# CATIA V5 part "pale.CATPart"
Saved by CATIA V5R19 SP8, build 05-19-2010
Part number: Pales et axe
Bounding box of the stored display mesh (mm): x -400.868 to 620.068, y -893.533 to 20.003, z -431.861 to 500
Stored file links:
  G:\EU_thinkMotion\CFAO_2010\St2M_groupe2\St2M_groupe2\npeyre\npeyre\pale.CATPart
  C:\Documents and Settings\Niels\Mes documents\IFMA\2A\Calculs et CFAO\Modélisation eolienne axe vertical\eolienne avec train reducteur\assemblage.CATProduct
  G:\EU_thinkMotion\CFAO_2010\St2M_groupe2\St2M_groupe2\npeyre\npeyre\alesage axe rotor.CATPart
  G:\EU_thinkMotion\CFAO_2010\St2M_groupe2\St2M_groupe2\npeyre\npeyre\sortie vers generateur.CATPart
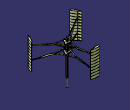
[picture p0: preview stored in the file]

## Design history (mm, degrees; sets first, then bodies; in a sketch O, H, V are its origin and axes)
Parameters
  `Longueur pale suivant Z` = 500 mm
  `Distance pale axe` = 500 mm
  `Diametre depart accroche pale` = 10 mm
  `Diametre interne accroche pale ` = 25 mm
  `Diametre des tiges d'accroche internes` = 11.1111 mm {= `Diametre interne accroche pale ` *4/9}
  `empatement des tiges d'accroche internes` = 130 mm
  `Hauteur du premier triangle rotor` = 600 mm
  `Diametre axe rotor` = 30 mm
  `Distance pale-division accroche (en % de la distance axe pale)` = 70 (ratio)
Sketch1 on xy-plane, origin (0, 0, 0), H (1, 0, 0), V (0, 1, 0)
  line L1 (34.746, -500) -> (164.746, -500)
  point P2 (164.746, -500)
  line L2 (164.746, -500) -> (99.746, -612.5833)
  line L3 (99.746, -612.5833) -> (34.746, -500)
  reference projected line E1 (-5.254, -500) -> (194.746, -500) from Sketch2.L3
  reference projected point E2 (164.746, -500) from vertex [element of Sketch2 | element of Sketch2]
  length L2 = 130 {= `empatement des tiges d'accroche internes`}
  length L3 = 130 {= `empatement des tiges d'accroche internes`}
  length L1 = 130 {= `empatement des tiges d'accroche internes`}
  horizontal: L1 H
  coincidence: L1 E1, P2 E2
Sketch2 on Plane3, origin (0, -500, 0), H (-1, 0, 0), V (0, 0, 1)
  line L1 (-34.746, 157.0283) -> (-164.746, 157.0283)
  line L2 (-164.746, 157.0283) -> (-164.746, 168.1394)
  line L3 (-164.746, 168.1394) -> (-34.746, 168.1394)
  line L4 (-34.746, 168.1394) -> (-34.746, 157.0283)
  reference projected circle E1 centre (-105.3016, 162.5839) radius 5.5556 from Sketch5.A1
  reference projected circle E2 centre (-105.3016, 162.5839) radius 5.5556 from Sketch5.A1
  reference projected line E3 through (-99.746, 0) direction (0, 1) from Line1
  distance L4 L2 = 130 {= `empatement des tiges d'accroche internes`}
  distance L4 E3 = 65 {= `empatement des tiges d'accroche internes` /2}
  horizontal: L1 H, L3 H
  vertical: L2 V, L4 V
  tangency: E1 L3, L1 E2
Body1 (main body)
  Point1: type OnPlane, Support xy-plane, H 0 {= `détruit_facteur d'echelle du profil` *0mm}, V 0 {= `détruit_facteur d'echelle du profil` *0mm}, Direction (1, 0, 0)
  Point2: type OnPlane, Support xy-plane, H 16.791 {= `détruit_facteur d'echelle du profil` *16.791mm}, V 14.593 {= `détruit_facteur d'echelle du profil` *14.593mm}, Direction (1, 0, 0)
  Point3: type OnPlane, Support xy-plane, H 59.666 {= `détruit_facteur d'echelle du profil` *59.666mm}, V 19.725 {= `détruit_facteur d'echelle du profil` *19.725mm}, Direction (1, 0, 0)
  Point4: type OnPlane, Support xy-plane, H 104.76 {= `détruit_facteur d'echelle du profil` *104.76mm}, V 16.638 {= `détruit_facteur d'echelle du profil` *16.638mm}, Direction (1, 0, 0)
  Point5: type OnPlane, Support xy-plane, H 169.79 {= `détruit_facteur d'echelle du profil` *169.79mm}, V 0 {= `détruit_facteur d'echelle du profil` *0mm}, Direction (1, 0, 0)
  Point6: type OnPlane, Support xy-plane, H 114.746 {= `détruit_facteur d'echelle du profil` *114.746mm}, V -8.578 {= `détruit_facteur d'echelle du profil` *-8.578mm}, Direction (1, 0, 0)
  Point7: type OnPlane, Support xy-plane, H 55.672 {= `détruit_facteur d'echelle du profil` *55.672mm}, V -13.026 {= `détruit_facteur d'echelle du profil` *-13.026mm}, Direction (1, 0, 0)
  Point8: type OnPlane, Support xy-plane, H 17.764 {= `détruit_facteur d'echelle du profil` *17.764mm}, V -11.11 {= `détruit_facteur d'echelle du profil` *-11.11mm}, Direction (1, 0, 0)
  Curve1: Elements (Point1; Point2; Point3; Point4; Point5; Point6; Point7; Point8), SemiClosure Point5
  Fill1: Boundary Curve1
  RectPattern1: of Fill1, direction 1 instances 11, spacing 50 {= `Longueur pale suivant Z` /10}, along Z axis
  Split1: ToCut Curve1, Cutting (Point6; Point5)
  Extrude1: Element1 {split ToCut Curve1, Cutting (Point6; Point5)}, Lim1 500 {= `Longueur pale suivant Z`}, Lim2 0, Direction (0, 0, 1)
  Plane1: type Offset, RefPlane zx-plane, Offset -15 {= `détruit_facteur d'echelle du profil` *-15mm}
  Sketch3 on Plane1, origin (0, -15, 0), H (-1, 0, 0), V (0, 0, 1)
    circle A1 centre (-99.746, 125) radius 5
    point P1 (-99.746, 125)
    reference projected line E1 (0, 0) -> (-169.9299, 0) from edge of Curve1
    reference projected line E2 (-114.746, 1000) -> (-114.746, 0) from edge of Extrude1
    distance P1 E1 = 125 {= `Longueur pale suivant Z` *1/4}
    distance E2 A1 = 10 {= `détruit_facteur d'echelle du profil` *10mm}
    radius A1 = 5 {= `Diametre depart accroche pale` /2}
  Extrude2: Element1 Sketch3, Lim1 0, Lim2 10, Direction Plane1, FirstUpto Extrude1
  Plane2: type Offset, RefPlane zx-plane, Offset 350 {= `Distance pale axe` *`Distance pale-division accroche (en % de la distance axe pale)`}, reversed
  Point9: type Center, Curve Sketch3
  Line1: type PtDir, RefPoint Point9, Direction Sketch3.V, Start 0, End 20
  Sketch4 on Plane2, origin (0, -350, 0), H (0, 0, 1), V (1, 0, 0)
    circle A1 centre (166.6667, 99.746) radius 12.5
    point P1 (166.6667, 99.746)
    reference projected line E1 through (0, 99.746) direction (1, 0) from Line1
    reference projected line E2 (0, 0) -> (0, 169.9299) from edge of Curve1
    distance P1 E2 = 166.6667 {= `Longueur pale suivant Z` *1/3}
    radius A1 = 12.5 {= `Diametre interne accroche pale `/2}
    coincidence: P1 E1
  Extrude3: Element1 Sketch4, Lim1 0, Lim2 4, Direction Plane2
  Blend1: StartLimit {blendlimit Curve edge of Extrude2, Point {extremum Reference edge of Extrude2, Direction (1, 2, 3)}, Support Extrude2}, EndLimit {blendlimit Curve Sketch4, Point {extremum Reference Sketch4, Direction (1, 2, 3)}, Support Extrude3}
  Fill2: Boundary edge of Extrude3
  Sketch5 on Fill2, origin (0, -354, 0), H (-1, 0, 0), V (0, 0, 1)
    circle A1 centre (-105.3016, 162.5839) radius 5.5556
    point P1 (-105.3016, 162.5839)
    point P2 (-94.1904, 162.5839)
    circle A2 centre (-94.1904, 162.5839) radius 5.5556
    circle A3 centre (-99.746, 172.2064) radius 5.5556
    point P3 (-99.746, 172.2064)
    reference projected line E1 through (-99.746, 0) direction (0, 1) from Line1
    reference projected circle E2 centre (-99.746, 166.6667) radius 12.5 from Sketch4.A1
    reference projected circle E3 centre (-99.746, 166.6667) radius 12.5 from Sketch4.A1
    axis line L1 (-105.3016, 162.5839) -> (-94.1904, 162.5839)
    point P4 (-105.3016, 162.5839)
    point P5 (-94.1904, 162.5839)
    point P6 (-99.746, 172.2064)
    radius A1 = 5.5556 {= `Diametre des tiges d'accroche internes`/2}
    radius A2 = 5.5556 {= `Diametre des tiges d'accroche internes` /2}
    radius A3 = 5.5556 {= `Diametre des tiges d'accroche internes` /2}
    distance P1 E2 = 5.6056 {= (`Diametre des tiges d'accroche internes`+0.1mm)/2}
    distance P2 E3 = 5.6056 {= (`Diametre des tiges d'accroche internes`+0.1mm)/2}
    distance P5 P6 = 11.1111 {= `Diametre des tiges d'accroche internes`}
    distance P5 P4 = 11.1111 {= `Diametre des tiges d'accroche internes`}
    coincidence: P3 E1, P5 P2, P4 P1, P6 P3
    horizontal: L1 H
  Plane3: type Offset, RefPlane zx-plane, Offset 500 {= `Distance pale axe`}, reversed
  SolidCombine1: FirstComponentProfile Sketch1, FirstComponentDirection Sketch1, SecondComponentProfile Sketch2, SecondComponentDirection Sketch2
  Sketch6 on face of SolidCombine1 from Sketch2.L3, origin (0, 0, 168.1394), H (1, 0, 0), V (0, 1, 0)
    circle A1 centre (99.746, -537.5278) radius 15
    point P1 (99.746, -537.5278)
    reference projected line E1 (-5.254, -500) -> (194.746, -500) from edge [face of SolidCombine1 from Sketch2.L3 | face of SolidCombine1 from Sketch1.L1]
    reference projected line E2 (241.2524, -857.6795) -> (341.2524, -1030.8846) from edge [face of SolidCombine1 from Sketch1.L3 | face of SolidCombine1 from Sketch2.L3]
    distance P1 E1 = 37.5278 {= `empatement des tiges d'accroche internes` *sqrt(3)/6}
    distance E2 P1 = 37.5278 {= `empatement des tiges d'accroche internes` *sqrt(3)/6}
    radius A1 = 15 {= `Diametre axe rotor` /2}
  Pad1: profile Sketch6, direction (0, 0, 1), length 600 {= `Hauteur du premier triangle rotor`}, mirrored extent
  Sketch7 on face of SolidCombine1 from Sketch1.L1, origin (0, -500, 0), H (-1, 0, 0), V (0, 0, 1)
    circle A1 centre (-40.3016, 162.5839) radius 5.5556
    point P1 (-40.3016, 162.5839)
    reference projected line E1 (-34.746, 321.9041) -> (-34.746, 335.2374) from edge [face of SolidCombine1 from Sketch1.L3 | face of SolidCombine1 from Sketch1.L1]
    reference projected line E2 (5.254, 168.1394) -> (-194.746, 168.1394) from edge [face of SolidCombine1 from Sketch2.L3 | face of SolidCombine1 from Sketch1.L1]
    reference projected line E3 (5.254, 157.0283) -> (-194.746, 157.0283) from edge [face of SolidCombine1 from Sketch1.L1 | face of SolidCombine1 from Sketch2.L1]
    point P2 (-40.3016, 162.5839)
    circle A2 centre (-159.1904, 162.5839) radius 5.5556
    point P3 (-159.1904, 162.5839)
    reference projected line E4 (5.254, 168.1394) -> (-194.746, 168.1394) from edge [face of SolidCombine1 from Sketch2.L3 | face of SolidCombine1 from Sketch1.L1]
    reference projected line E5 (5.254, 157.0283) -> (-194.746, 157.0283) from edge [face of SolidCombine1 from Sketch1.L1 | face of SolidCombine1 from Sketch2.L1]
    reference projected line E6 (-164.746, 321.9041) -> (-164.746, 335.2374) from edge [face of SolidCombine1 from Sketch1.L1 | face of SolidCombine1 from Sketch1.L2]
    point P4 (-159.1904, 162.5839)
    tangency: A1 E1, A1 E2, A1 E3, A2 E4, A2 E5, A2 E6
    coincidence: P2 P1, P4 P3
  Line2: type PtPt, FirstPoint Sketch5.P5, SecondPoint Sketch7.P2
  Extrude4: Element1 Sketch5.A2, Lim1 0, Lim2 4, Direction Line2, FirstUpto face of SolidCombine1 from Sketch1.L1
  Line3: type PtPt, FirstPoint Sketch5.P4, SecondPoint Sketch7.P4
  Extrude5: Element1 Sketch5.A1, Lim1 0, Lim2 4, Direction Line3, FirstUpto face of SolidCombine1 from Sketch1.L1
  Sketch8 on Plane3, origin (0, -500, 0), H (-1, 0, 0), V (0, 0, 1)
    line L1 (-94.1904, 236.6667) -> (-105.3016, 236.6667)
    line L2 (-105.3016, 236.6667) -> (-105.3016, 250)
    line L3 (-105.3016, 250) -> (-94.1904, 250)
    line L4 (-94.1904, 250) -> (-94.1904, 236.6667)
    reference projected line E1 (0, 0) -> (-169.9299, 0) from edge of Curve1
    point P5 (-99.746, 319.4582)
    reference projected line E2 through (-99.746, 0) direction (0, 1) from axis of face of Pad1 from Sketch6.A1
    length L1 = 11.1111 {= `Diametre des tiges d'accroche internes`}
    distance L3 E1 = 250 {= `Longueur pale suivant Z` /2}
    distance P5 L2 = 5.5556 {= `Diametre des tiges d'accroche internes` /2}
    horizontal: L1 H, L3 H
    vertical: L2 V, L4 V
    coincidence: P5 E2
  Pad2: profile Sketch8, direction (0, -1, 0), up to face of Pad1 from Sketch6.A1
  Point10: type OnSurface, Support start face of Pad2, Length 0, Direction Y axis
  Line4: type PtPt, FirstPoint Point10, SecondPoint Sketch5.P6
  Extrude6: Element1 Sketch5.A3, Lim1 0, Lim2 4, Direction Line4, FirstUpto start face of Pad2, SecondUpto vertex [face of Fill2]
  Blend2: StartLimit {blendlimit Curve edge of Extrude6, Point {extremum Reference edge of Extrude6, Direction (1, 2, 3)}, Support Extrude6}, EndLimit {blendlimit Curve Sketch5.A3, Point {extremum Reference Sketch5.A3, Direction (1, 2, 3)}, Support Fill2}
  MultiSel1
  Plane4: type Offset, RefPlane xy-plane, Offset 400 {= `Longueur pale suivant Z` *0.8}
  Sketch9 on Plane4, origin (0, 0, 400), H (1, 0, 0), V (0, 1, 0)
    line L1 (0, 0) -> (0, -1000)
    length L1 = 1000 {= `Distance pale axe` *2}
    vertical: L1 V
  Extrude7: Element1 Sketch9, Lim1 0, Lim2 500 {= `Distance pale axe`}, Direction Sketch7.H
  Split2: ToCut {symmetry ToTransfor Pad2, Reference face of Pad2 from Sketch8.L3}, Cutting Extrude7, Intersections {intersect ToIntersect1 {symmetry ToTransfor Pad2, Reference face of Pad2 from Sketch8.L3}, ToIntersect2 Extrude7}
  Split3: SplitPlane Extrude7
  AxisLine1: Element {intersect ToIntersect1 {symmetry ToTransfor Pad2, Reference face of Pad2 from Sketch8.L3}, ToIntersect2 Extrude7}
  Join1: Elements (Extrude1; RectPattern1; {symmetry ToTransfor Extrude2, Reference face of Pad2 from Sketch8.L3}; {symmetry ToTransfor Blend1, Reference face of Pad2 from Sketch8.L3}; {symmetry ToTransfor Extrude3, Reference face of Pad2 from Sketch8.L3}; {symmetry ToTransfor Blend2, Reference face of Pad2 from Sketch8.L3}; {symmetry ToTransfor Extrude6, Reference face of Pad2 from Sketch8.L3}; {symmetry ToTransfor Extrude4, Reference face of Pad2 from Sketch8.L3}; Extrude4; Extrude3; Blend1; Extrude2; Blend2; {symmetry ToTransfor Extrude5, Reference face of Pad2 from Sketch8.L3}; Extrude5; Extrude6; Split2; start face of Pad2; face of Pad2 from Sketch8.L4; face of Pad2 from Sketch8.L1; face of Pad2 from Sketch8.L2; Fill1; Fill2; {symmetry ToTransfor Fill2, Reference face of Pad2 from Sketch8.L3})
  CircPattern1: of Join1, instances 3, angular step 120, axis from AxisLine1
  Fillet1: radius 0.7, on edge [face of Extrude3 from Sketch4.A1 | face of Fill2]; edge [face of MultiSel1 | face of MultiSel1]
  Fillet2: radius 0.7, on edge [face of CircPattern1 | face of CircPattern1] (x3); face of CircPattern1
